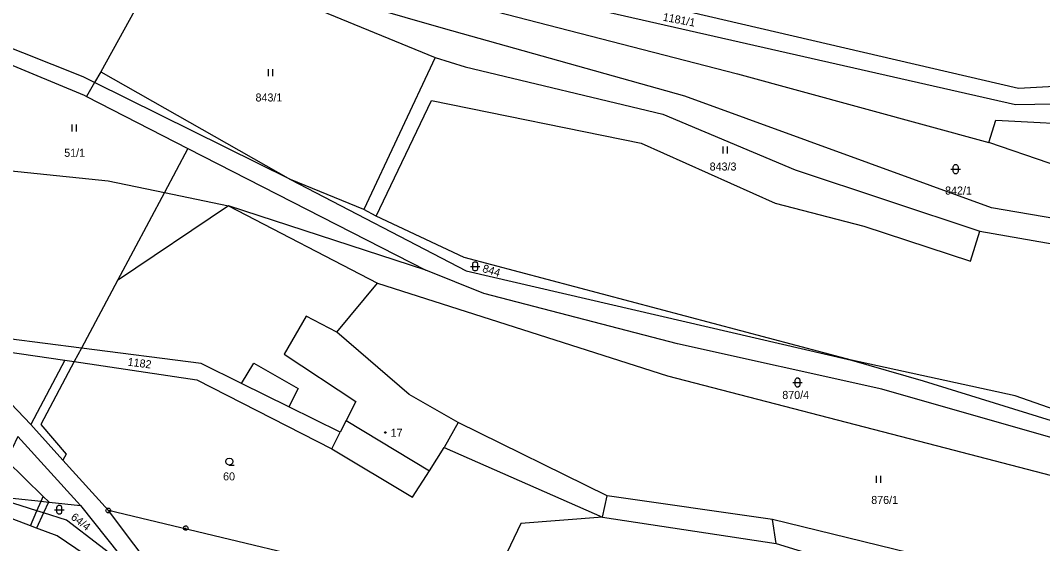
# Model space of a CAD drawing. Extents: x -694465 to -690527, y -983694 to -978978.
# Drawn here: x -691661.7 to -691444.6, y -980898.4 to -980787.1 of the extents above; entities that cross this region are included whole.
import ezdxf

# ---------------------------------------------------------------- set-up
doc = ezdxf.new("R2010")
doc.units = 0
for name, color, linetype in [('Vrstva 1', 7, 'Continuous'), ('Vrstva 18', 7, 'Continuous'), ('Vrstva 19', 7, 'Continuous'), ('Vrstva 24', 7, 'Continuous'), ('Vrstva 25', 7, 'Continuous')]:
    doc.layers.add(name, color=color, linetype=linetype)

msp = doc.modelspace()

# ---------------------------------------------------------------- linework, layer by layer
at = {"layer": 'Vrstva 1'}
msp.add_line((-691501.17, -980898.31), (-691501.9, -980893.26), dxfattribs=at)
for points in [[(-691627.85, -980772.68), (-691573.6, -980794.97)], [(-691275.624, -980860.301), (-691294.258, -980854.732), (-691315.93, -980853.51), (-691345.843, -980849.845), (-691378.808, -980840.072), (-691455.422, -980826.94), (-691520.575, -980803.197), (-691571.855, -980788.843), (-691627.85, -980772.68)], [(-691449.67, -980801.62), (-691552.39, -980777.6)], [(-691634.84, -980780.26), (-691644.63, -980798.04)], [(-691450.28, -980805.05), (-691552.45, -980781.84)], [(-691560.74, -980785.24), (-691509.4, -980798.45)], [(-691648.4, -980799.1), (-691680.7, -980786.25)], [(-691671.74, -980793.24), (-691648.14, -980803.03)], [(-691573.6, -980794.97), (-691588.72, -980827.31)], [(-691573.6, -980794.97), (-691567.23, -980796.98)], [(-691644.63, -980798.04), (-691645.948, -980800.314)], [(-691644.63, -980798.04), (-691604.31, -980820.93)], [(-691567.23, -980796.98), (-691525.21, -980807.02)], [(-691645.948, -980800.314), (-691648.4, -980799.1)], [(-691645.948, -980800.314), (-691647.664, -980803.274)], [(-691604.31, -980820.93), (-691645.948, -980800.314)], [(-691509.4, -980798.45), (-691456, -980813.05)], [(-691421.56, -980800.02), (-691449.67, -980801.62)], [(-691648.14, -980803.03), (-691647.664, -980803.274)], [(-691647.664, -980803.274), (-691626.112, -980814.316)], [(-691586.1, -980828.71), (-691574.38, -980804.16)], [(-691574.38, -980804.16), (-691529.86, -980813.19)], [(-691421.63, -980804.58), (-691450.28, -980805.05)], [(-691525.21, -980807.02), (-691497.13, -980818.86)], [(-691456, -980813.05), (-691454.49, -980808.35)], [(-691454.49, -980808.35), (-691390.12, -980811.75)], [(-691529.86, -980813.19), (-691501.4, -980826)], [(-691417.54, -980826.23), (-691456, -980813.05)], [(-691626.112, -980814.316), (-691631.126, -980823.728)], [(-691626.112, -980814.316), (-691575.55, -980840.22)], [(-691679.47, -980817.49), (-691643.09, -980821.24)], [(-691497.13, -980818.86), (-691457.87, -980831.9)], [(-691643.09, -980821.24), (-691631.126, -980823.728)], [(-691588.72, -980827.31), (-691604.31, -980820.93)], [(-691604.31, -980820.93), (-691566.98, -980840.34)], [(-691631.126, -980823.728), (-691641.092, -980842.436)], [(-691631.126, -980823.728), (-691617.51, -980826.56)], [(-691617.51, -980826.56), (-691641.092, -980842.436)], [(-691617.51, -980826.56), (-691585.83, -980842.95)], [(-691575.55, -980840.22), (-691617.51, -980826.56)], [(-691501.4, -980826), (-691482.5, -980830.83)], [(-691586.1, -980828.71), (-691588.72, -980827.31)], [(-691567.42, -980837.53), (-691586.1, -980828.71)], [(-691482.5, -980830.83), (-691459.89, -980838.27)], [(-691459.89, -980838.27), (-691457.87, -980831.9)], [(-691457.87, -980831.9), (-691371.67, -980847.05)], [(-691485.16, -980859.34), (-691567.42, -980837.53)], [(-691563.29, -980845.19), (-691575.55, -980840.22)], [(-691566.98, -980840.34), (-691485.16, -980859.34)], [(-691641.092, -980842.436), (-691648.739, -980856.791)], [(-691594.46, -980853.39), (-691585.83, -980842.95)], [(-691585.83, -980842.95), (-691524.26, -980862.7)], [(-691522.08, -980855.86), (-691563.29, -980845.19)], [(-691600.97, -980850.01), (-691605.65, -980858.1)], [(-691594.46, -980853.39), (-691600.97, -980850.01)], [(-691648.739, -980856.791), (-691664.18, -980854.79)], [(-691579.13, -980866.64), (-691594.46, -980853.39)], [(-691648.739, -980856.791), (-691650.268, -980859.662)], [(-691623.29, -980860.09), (-691648.739, -980856.791)], [(-691478.69, -980865.52), (-691522.08, -980855.86)], [(-691664.86, -980857.5), (-691652.26, -980859.366)], [(-691605.65, -980858.1), (-691590.44, -980868.16)], [(-691652.26, -980859.366), (-691659.505, -980873.059)], [(-691650.268, -980859.662), (-691657.4, -980873.05), (-691651.977, -980879.327), (-691652.695, -980880.585)], [(-691652.26, -980859.366), (-691650.268, -980859.662)], [(-691650.268, -980859.662), (-691624.22, -980863.52)], [(-691614.71, -980864.334), (-691623.29, -980860.09)], [(-691614.71, -980864.334), (-691612.144, -980860.01), (-691602.682, -980865.355), (-691604.657, -980869.306)], [(-691450.38, -980866.96), (-691485.16, -980859.34)], [(-691485.16, -980859.34), (-691469.94, -980863.72)], [(-691524.26, -980862.7), (-691465.27, -980878.02)], [(-691659.505, -980873.059), (-691668.17, -980864)], [(-691624.22, -980863.52), (-691595.55, -980878.24)], [(-691604.657, -980869.306), (-691614.71, -980864.334)], [(-691439.32, -980876.79), (-691478.69, -980865.52)], [(-691469.94, -980863.72), (-691379.21, -980891.89)], [(-691568.74, -980872.63), (-691579.13, -980866.64)], [(-691379.21, -980891.89), (-691450.38, -980866.96)], [(-691593.81, -980874.67), (-691604.657, -980869.306)], [(-691590.44, -980868.16), (-691592.531, -980872.2)], [(-691658.93, -980873.66), (-691659.505, -980873.059)], [(-691652.695, -980880.585), (-691658.93, -980873.66)], [(-691592.531, -980872.2), (-691593.81, -980874.67)], [(-691592.531, -980872.2), (-691574.834, -980882.881)], [(-691568.74, -980872.63), (-691571.69, -980877.95)], [(-691537.04, -980888.2), (-691568.74, -980872.63)], [(-691662.24, -980875.61), (-691664.64, -980880.66), (-691656.874, -980888.313)], [(-691648.93, -980890.28), (-691662.24, -980875.61)], [(-691595.55, -980878.24), (-691593.81, -980874.67)], [(-691595.55, -980878.24), (-691578.41, -980888.49)], [(-691574.834, -980882.881), (-691571.69, -980877.95)], [(-691571.69, -980877.95), (-691538.06, -980892.74)], [(-691465.27, -980878.02), (-691380.37, -980900.11)], [(-691643.03, -980891.32), (-691652.695, -980880.585)], [(-691578.41, -980888.49), (-691574.834, -980882.881)], [(-691658.209, -980891.367), (-691668.27, -980888.17)], [(-691668.27, -980888.17), (-691657.333, -980889.363)], [(-691658.209, -980891.367), (-691657.333, -980889.363)], [(-691657.333, -980889.363), (-691656.874, -980888.313)], [(-691657.333, -980889.363), (-691655.724, -980889.539)], [(-691656.874, -980888.313), (-691655.694, -980889.476)], [(-691655.724, -980889.539), (-691656.787, -980891.819)], [(-691655.694, -980889.476), (-691655.724, -980889.539)], [(-691655.724, -980889.539), (-691655.619, -980889.55)], [(-691655.694, -980889.476), (-691655.619, -980889.55)], [(-691655.619, -980889.55), (-691648.93, -980890.28)], [(-691538.06, -980892.74), (-691537.04, -980888.2)], [(-691501.9, -980893.26), (-691537.04, -980888.2)], [(-691659.602, -980894.552), (-691668.95, -980891.04)], [(-691659.602, -980894.552), (-691658.209, -980891.367)], [(-691656.787, -980891.819), (-691658.209, -980891.367)], [(-691648.93, -980890.28), (-691637.93, -980904.12)], [(-691576.2, -980907.32), (-691643.03, -980891.32)], [(-691626.64, -980913.07), (-691643.03, -980891.32)], [(-691656.787, -980891.819), (-691658.291, -980895.044)], [(-691651.94, -980893.36), (-691656.787, -980891.819)], [(-691637.93, -980904.12), (-691651.94, -980893.36)], [(-691538.06, -980892.74), (-691555.37, -980894.1)], [(-691538.06, -980892.74), (-691501.17, -980898.31)], [(-691463.39, -980902.69), (-691501.9, -980893.26)], [(-691658.291, -980895.044), (-691659.602, -980894.552)], [(-691653.91, -980896.69), (-691658.291, -980895.044)], [(-691555.37, -980894.1), (-691563.54, -980911.18)], [(-691637.836, -980907.637), (-691653.91, -980896.69)], [(-691501.17, -980898.31), (-691465.09, -980909.38)]]:
    msp.add_lwpolyline(points, dxfattribs=at)
at = {"layer": 'Vrstva 24'}
for points in [[(-691642.876, -980890.844), (-691642.626, -980891.026), (-691642.53, -980891.32), (-691642.626, -980891.614), (-691642.876, -980891.796), (-691643.184, -980891.796), (-691643.434, -980891.614), (-691643.53, -980891.32), (-691643.434, -980891.026), (-691643.184, -980890.844)], [(-691626.436, -980894.574), (-691626.186, -980894.756), (-691626.09, -980895.05), (-691626.186, -980895.344), (-691626.436, -980895.526), (-691626.744, -980895.526), (-691626.994, -980895.344), (-691627.09, -980895.05), (-691626.994, -980894.756), (-691626.744, -980894.574)]]:
    msp.add_lwpolyline(points, close=True, dxfattribs=at)
for points in [[(-691643.149, -980891.32), (-691642.91, -980891.32)], [(-691626.709, -980895.05), (-691626.47, -980895.05)]]:
    msp.add_lwpolyline(points, dxfattribs=at)
at = {"layer": 'Vrstva 25'}
for points in [[(-691609.06, -980797.45), (-691609.06, -980798.95)], [(-691608.06, -980798.95), (-691608.06, -980797.45)], [(-691650.81, -980809.21), (-691650.81, -980810.71)], [(-691649.81, -980810.71), (-691649.81, -980809.21)], [(-691512.48, -980813.94), (-691512.48, -980815.44)], [(-691511.48, -980815.44), (-691511.48, -980813.94)], [(-691464.02, -980818.74), (-691462.02, -980818.74)], [(-691566.09, -980839.41), (-691564.09, -980839.41)], [(-691497.6, -980864.1), (-691495.6, -980864.1)], [(-691617.33, -980881.66), (-691617.705, -980881.559), (-691617.979, -980881.285), (-691618.08, -980880.91), (-691617.979, -980880.535), (-691617.705, -980880.261), (-691617.33, -980880.16), (-691616.955, -980880.261), (-691616.681, -980880.535), (-691616.58, -980880.91), (-691616.681, -980881.285), (-691616.955, -980881.559), (-691617.33, -980881.66), (-691616.33, -980881.661)], [(-691479.93, -980883.92), (-691479.93, -980885.42)], [(-691478.93, -980885.42), (-691478.93, -980883.92)], [(-691654.45, -980891.15), (-691652.45, -980891.15)]]:
    msp.add_lwpolyline(points, dxfattribs=at)
for points in [[(-691463.52, -980818.24), (-691463.425, -980817.946), (-691463.175, -980817.764), (-691462.865, -980817.764), (-691462.615, -980817.946), (-691462.52, -980818.24), (-691462.52, -980819.24), (-691462.615, -980819.534), (-691462.865, -980819.716), (-691463.175, -980819.716), (-691463.425, -980819.534), (-691463.52, -980819.24)], [(-691565.59, -980838.91), (-691565.495, -980838.616), (-691565.245, -980838.434), (-691564.935, -980838.434), (-691564.685, -980838.616), (-691564.59, -980838.91), (-691564.59, -980839.91), (-691564.685, -980840.204), (-691564.935, -980840.386), (-691565.245, -980840.386), (-691565.495, -980840.204), (-691565.59, -980839.91)], [(-691497.1, -980863.6), (-691497.005, -980863.306), (-691496.755, -980863.124), (-691496.445, -980863.124), (-691496.195, -980863.306), (-691496.1, -980863.6), (-691496.1, -980864.6), (-691496.195, -980864.894), (-691496.445, -980865.076), (-691496.755, -980865.076), (-691497.005, -980864.894), (-691497.1, -980864.6)], [(-691584.103, -980874.578), (-691584.015, -980874.73), (-691584.103, -980874.882), (-691584.277, -980874.882), (-691584.365, -980874.73), (-691584.277, -980874.578)], [(-691653.95, -980890.65), (-691653.855, -980890.356), (-691653.605, -980890.174), (-691653.295, -980890.174), (-691653.045, -980890.356), (-691652.95, -980890.65), (-691652.95, -980891.65), (-691653.045, -980891.944), (-691653.295, -980892.126), (-691653.605, -980892.126), (-691653.855, -980891.944), (-691653.95, -980891.65)]]:
    msp.add_lwpolyline(points, close=True, dxfattribs=at)

# ---------------------------------------------------------------- texts
at = {"layer": 'Vrstva 18'}
for s, rotation, p in [('1181/1', 349.21778, (-691525.338, -980787.144)), ('844', 342.91524, (-691563.693, -980840.558)), ('1182', 352.82741, (-691639.002, -980860.504)), ('64/4', 322.11687, (-691651.148, -980893.019))]:
    msp.add_text(s, height=1.7, rotation=rotation, dxfattribs=at).set_placement(p)
for s, p in [('843/1', (-691611.759, -980804.35)), ('51/1', (-691652.405, -980816.11)), ('843/3', (-691515.284, -980819.03)), ('842/1', (-691465.263, -980824.13)), ('870/4', (-691499.846, -980867.59)), ('60', (-691618.652, -980884.91)), ('876/1', (-691480.953, -980889.92))]:
    msp.add_text(s, height=1.7, dxfattribs=at).set_placement(p)
at = {"layer": 'Vrstva 19'}
msp.add_text('17', height=1.7, dxfattribs=at).set_placement((-691583.057, -980875.64))

doc.saveas('drawing.dxf')
